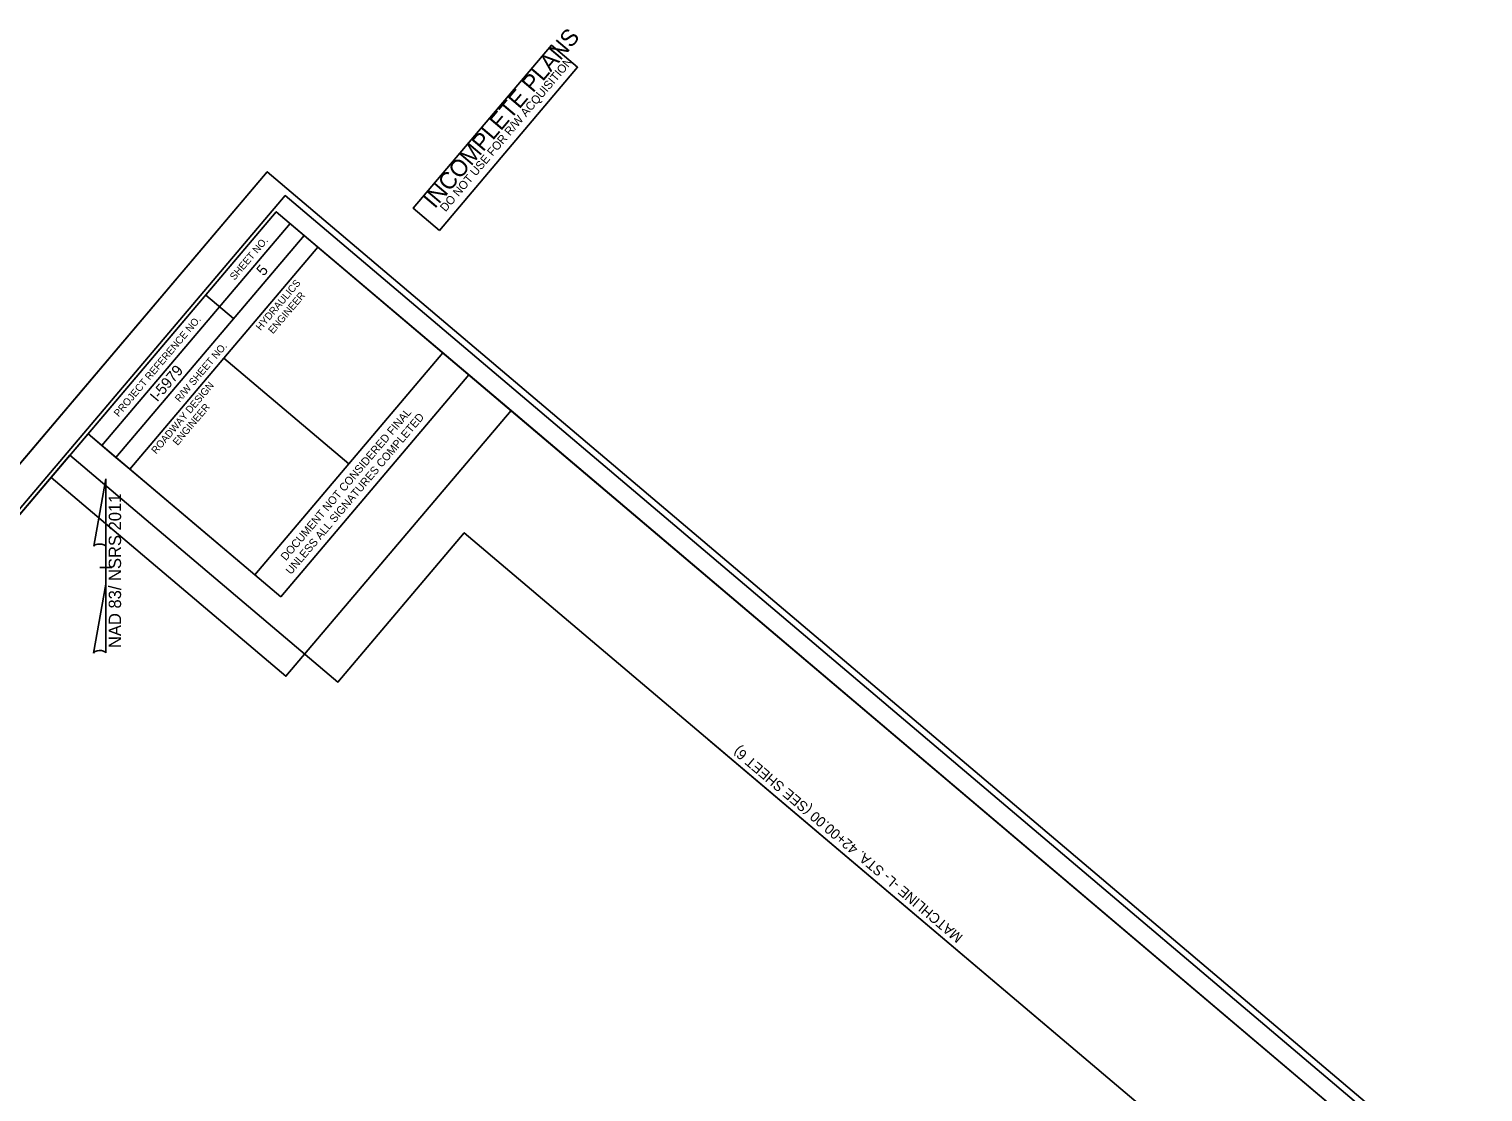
# Model space of a CAD drawing. Extents: x 1761124 to 1763803, y 421930 to 424918.
# Drawn here: x 1762804 to 1763803, y 424187 to 424918 of the extents above; entities that cross this region are included whole.
import ezdxf

# ---------------------------------------------------------------- set-up
doc = ezdxf.new("R2010")
doc.units = 0
for name, color, linetype in [('CTL Sheet Datum Description CELL', 7, 'Continuous'), ('Exist Hydro Stream or Body of Water', 7, 'Continuous'), ('Exist Other Culture Sign Post CELL', 7, 'Continuous'), ('Exist Roads Change in Surface', 7, 'Continuous'), ('Exist Roads Change in Surface Leader', 7, 'Continuous'), ('Exist Roads Change in Surface Text', 7, 'Continuous'), ('Exist Roads Curbs', 7, 'Continuous'), ('Exist Roads Curbs Leader', 7, 'Continuous'), ('Exist Roads EOP', 7, 'Continuous'), ('Exist Roads EOP Other', 7, 'Continuous'), ('Exist Roads EOP Text', 7, 'Continuous'), ('Exist Roads Soil', 7, 'Continuous'), ('Exist Structure Major Deck Tunnel Box Culvert', 7, 'Continuous')]:
    doc.layers.add(name, color=color, linetype=linetype)

msp = doc.modelspace()

# ---------------------------------------------------------------- linework, layer by layer
at = {"layer": 'CTL Sheet Datum Description CELL'}
msp.add_lwpolyline([(1762004.42, 423647.67), (1762290.12, 423405.67), (1762365.05, 423494.02), (1762431.11, 423438.06), (1762620.91, 423277.27), (1762680.29, 423186), (1762663.1, 423167.95), (1762828.75, 422996.34), (1763720.34, 424048.79), (1763103.2, 424571.6), (1763016.39, 424468.96), (1762832.28, 424624.92), (1762079.3, 423736.09)], close=True, dxfattribs=at)
at = {"layer": 'Exist Other Culture Sign Post CELL'}
msp.add_line((1763514.22, 424223.41), (1763270.98, 424429.46), dxfattribs=at)
at = {"layer": 'Exist Roads Change in Surface'}
msp.add_lwpolyline([(1762715.14, 422827.41), (1763803.34, 424111.93), (1762967.84, 424819.73), (1761879.65, 423535.21)], close=True, dxfattribs=at)
at = {"layer": 'Exist Roads Change in Surface Leader'}
msp.add_lwpolyline([(1763086.15, 424779.45), (1763068.22, 424794.64), (1763163.24, 424906.81), (1763181.17, 424891.62)], close=True, dxfattribs=at)
at = {"layer": 'Exist Roads Change in Surface Text'}
msp.add_line((1762967.84, 424819.73), (1761879.65, 423535.21), dxfattribs=at)
at = {"layer": 'Exist Roads Curbs Leader'}
msp.add_line((1762856.36, 424540.5), (1762856.36, 424540.5), dxfattribs=at)
at = {"layer": 'Exist Roads EOP'}
for p, q in [((1762959.2, 424542.6), (1763088.5, 424695.23)), ((1762959.2, 424542.6), (1763088.5, 424695.23)), ((1763088.51, 424695.22), (1763106.44, 424680.03)), ((1763088.51, 424695.22), (1763106.44, 424680.03)), ((1763106.43, 424680.04), (1762977.13, 424527.41)), ((1763106.43, 424680.04), (1762977.13, 424527.41)), ((1762977.13, 424527.41), (1762959.2, 424542.6)), ((1762977.13, 424527.41), (1762959.2, 424542.6))]:
    msp.add_line(p, q, dxfattribs=at)
at = {"layer": 'Exist Roads EOP Other'}
for p, q in [((1762854.26, 424631.47), (1762983.58, 424784.1)), ((1762863.83, 424623.37), (1762993.12, 424776.02)), ((1762863.83, 424623.37), (1762993.12, 424776.02)), ((1762925.56, 424734.93), (1762944.66, 424718.81)), ((1762938.03, 424691.64), (1763023.85, 424618.96)), ((1762863.83, 424623.37), (1762873.36, 424615.3))]:
    msp.add_line(p, q, dxfattribs=at)
for points in [[(1762974.03, 424792.24), (1762004.42, 423647.7), (1762805.58, 422968.99), (1763775.17, 424113.51)], [(1762844.69, 424639.59), (1762974.03, 424792.24), (1762993.12, 424776.02), (1762863.83, 424623.37)], [(1762938.03, 424691.64), (1763002.66, 424767.94), (1763088.51, 424695.22), (1763023.88, 424618.91)], [(1762805.58, 422968.99), (1762004.42, 423647.67), (1762844.69, 424639.59), (1762959.2, 424542.6), (1763088.51, 424695.22), (1763775.17, 424113.51)], [(1762873.36, 424615.3), (1762938.03, 424691.64), (1763023.88, 424618.91), (1762959.2, 424542.6)]]:
    msp.add_lwpolyline(points, close=True, dxfattribs=at)
at = {"layer": 'Exist Roads EOP Text'}
for p, q in [((1762848.62, 424562.37), (1762856.82, 424608.72)), ((1762856.87, 424608.72), (1762856.82, 424608.72)), ((1762856.87, 424608.72), (1762856.82, 424608.72)), ((1762856.87, 424608.72), (1762856.87, 424560.92)), ((1762856.87, 424536.12), (1762856.87, 424562.32)), ((1762856.87, 424560.92), (1762856.87, 424562.27)), ((1762852.87, 424547.72), (1762852.82, 424547.72)), ((1762856.42, 424547.72), (1762852.87, 424547.72)), ((1762852.92, 424547.72), (1762860.92, 424547.72)), ((1762856.87, 424536.12), (1762848.52, 424488.87)), ((1762856.92, 424489.07), (1762856.87, 424536.12))]:
    msp.add_line(p, q, dxfattribs=at)
for centre, start_param, end_param in [((1762852.76, 424561.88), 0.216388, 2.908219), ((1762852.76, 424488.71), 0.201328, 3.141593)]:
    msp.add_ellipse(centre, major_axis=(4.23, -0.03), ratio=0.461098, start_param=start_param, end_param=end_param, dxfattribs=at)
at = {"layer": 'Exist Roads Soil'}
msp.add_lwpolyline([(1762708.28, 422850.26), (1763785.15, 424121.43), (1762980.19, 424803.37), (1761903.31, 423532.2)], close=True, dxfattribs=at)
at = {"layer": 'Exist Structure Major Deck Tunnel Box Culvert'}
for points in [[(1762980.72, 424472.96), (1763135.39, 424655.53), (1762974.04, 424792.25), (1762819.36, 424609.66)], [(1762004.42, 423647.67), (1762805.58, 422968.99), (1763775.16, 424113.5), (1763135.37, 424655.51), (1762980.72, 424472.96), (1762819.36, 424609.66)]]:
    msp.add_lwpolyline(points, close=True, dxfattribs=at)

# ---------------------------------------------------------------- texts
at = {"layer": 'Exist Hydro Stream or Body of Water'}
msp.add_text('MATCHLINE -L- STA. 42+00.00 (SEE SHEET 6)', height=7, rotation=139.7301, dxfattribs=at).set_placement((1763446.44, 424294.38))
at = {"layer": 'Exist Roads Change in Surface Leader'}
for s, height, p in [('INCOMPLETE PLANS', 11.52, (1763083, 424793.85)), ('DO NOT USE FOR R/W ACQUISITION', 5.76, (1763090.41, 424791.83))]:
    msp.add_text(s, height=height, rotation=49.7301, dxfattribs=at).set_placement(p)
at = {"layer": 'Exist Roads Curbs'}
for s, p in [('5', (1762965.35, 424747.58)), ('I-5979', (1762892.2, 424661.13))]:
    msp.add_text(s, height=7.5, rotation=49.73011, dxfattribs=at).set_placement(p)
at = {"layer": 'Exist Roads EOP'}
for s, p in [('DOCUMENT NOT CONSIDERED FINAL', (1762980.71, 424551.99)), ('DOCUMENT NOT CONSIDERED FINAL', (1762980.71, 424551.99)), ('UNLESS ALL SIGNATURES COMPLETED', (1762984.15, 424542.43)), ('UNLESS ALL SIGNATURES COMPLETED', (1762984.15, 424542.43))]:
    msp.add_text(s, height=5.5, rotation=49.7301, dxfattribs=at).set_placement(p)
at = {"layer": 'Exist Roads EOP Other'}
for s, height, p in [('SHEET NO.', 5, (1762945.4, 424744.79)), ('HYDRAULICS', 5, (1762963.28, 424710.18)), ('ENGINEER', 5, (1762971.78, 424707.91)), ('PROJECT REFERENCE NO.', 5.0001, (1762865.7, 424650.89)), ('R/W SHEET NO.', 5.0001, (1762907.69, 424660.93)), ('ROADWAY DESIGN', 5.0001, (1762891.46, 424625.37)), ('ENGINEER', 5, (1762906.25, 424631.17))]:
    msp.add_text(s, height=height, rotation=49.73011, dxfattribs=at).set_placement(p)
at = {"layer": 'Exist Roads EOP Text'}
msp.add_text('NAD 83/ NSRS 2011', height=8.5, rotation=90, dxfattribs=at).set_placement((1762867.39, 424492.32))

doc.saveas('drawing.dxf')
